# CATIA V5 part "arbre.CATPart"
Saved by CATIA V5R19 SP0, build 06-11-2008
Part number: Part2.1
Bounding box of the stored display mesh (mm): x -24.865 to 24.865, y -81.67 to 138.33, z -24.997 to 24.997
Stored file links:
  F:\20\arbre.CATPart
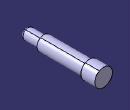
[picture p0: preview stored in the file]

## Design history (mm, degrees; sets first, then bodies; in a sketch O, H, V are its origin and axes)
Body1 (main body)
  Sketch1 on yz-plane, origin (0, 0, 0), H (0, 1, 0), V (0, 0, 1)
    point P1 (-81.6702, 0)
    line L1 (-81.6702, 0) -> (-81.6702, 15)
    line L2 (-81.6702, 15) -> (-31.6702, 15)
    line L3 (-31.6702, 15) -> (-31.6702, 20)
    line L4 (-31.6702, 20) -> (98.3298, 20)
    line L5 (98.3298, 20) -> (98.3298, 25)
    line L6 (98.3298, 25) -> (138.3298, 25)
    line L7 (138.3298, 25) -> (138.3298, 0)
    point P8 (138.3298, 0)
    length L4 = 130
    length L6 = 40
    length L2 = 50
    length L7 = 25
    length L1 = 15
    distance L4 H = 20
    coincidence: P1 H, P8 H
    vertical: L1 V, L3 V, L5 V, L7 V
    horizontal: L2 H, L4 H, L6 H
  Shaft1: profile Sketch1, axis Sketch1.H, angle 360
  Fillet1: radius 5, on edge [face of Shaft1 from Sketch1.L1 | face of Shaft1 from Sketch1.L2]
  Point1: type Center, Curve edge [face of Shaft1 from Sketch1.L6 | face of Shaft1 from Sketch1.L7]
  Line1: type Normal, RefSkin face of Shaft1 from Sketch1.L7, Start 0, End 20, RefPoint Point1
